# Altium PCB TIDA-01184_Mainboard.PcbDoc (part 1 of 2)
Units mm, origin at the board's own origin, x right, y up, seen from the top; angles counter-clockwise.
Board outline 127 x 101.6 mm, 4 copper layers (L1 - TOP Component, L2 - GND, L3 - VCC, L4 - BOTTOM Solder), stack 0.844 mm thick; 127 components, 87 nets, 414 pads, 196 vias.
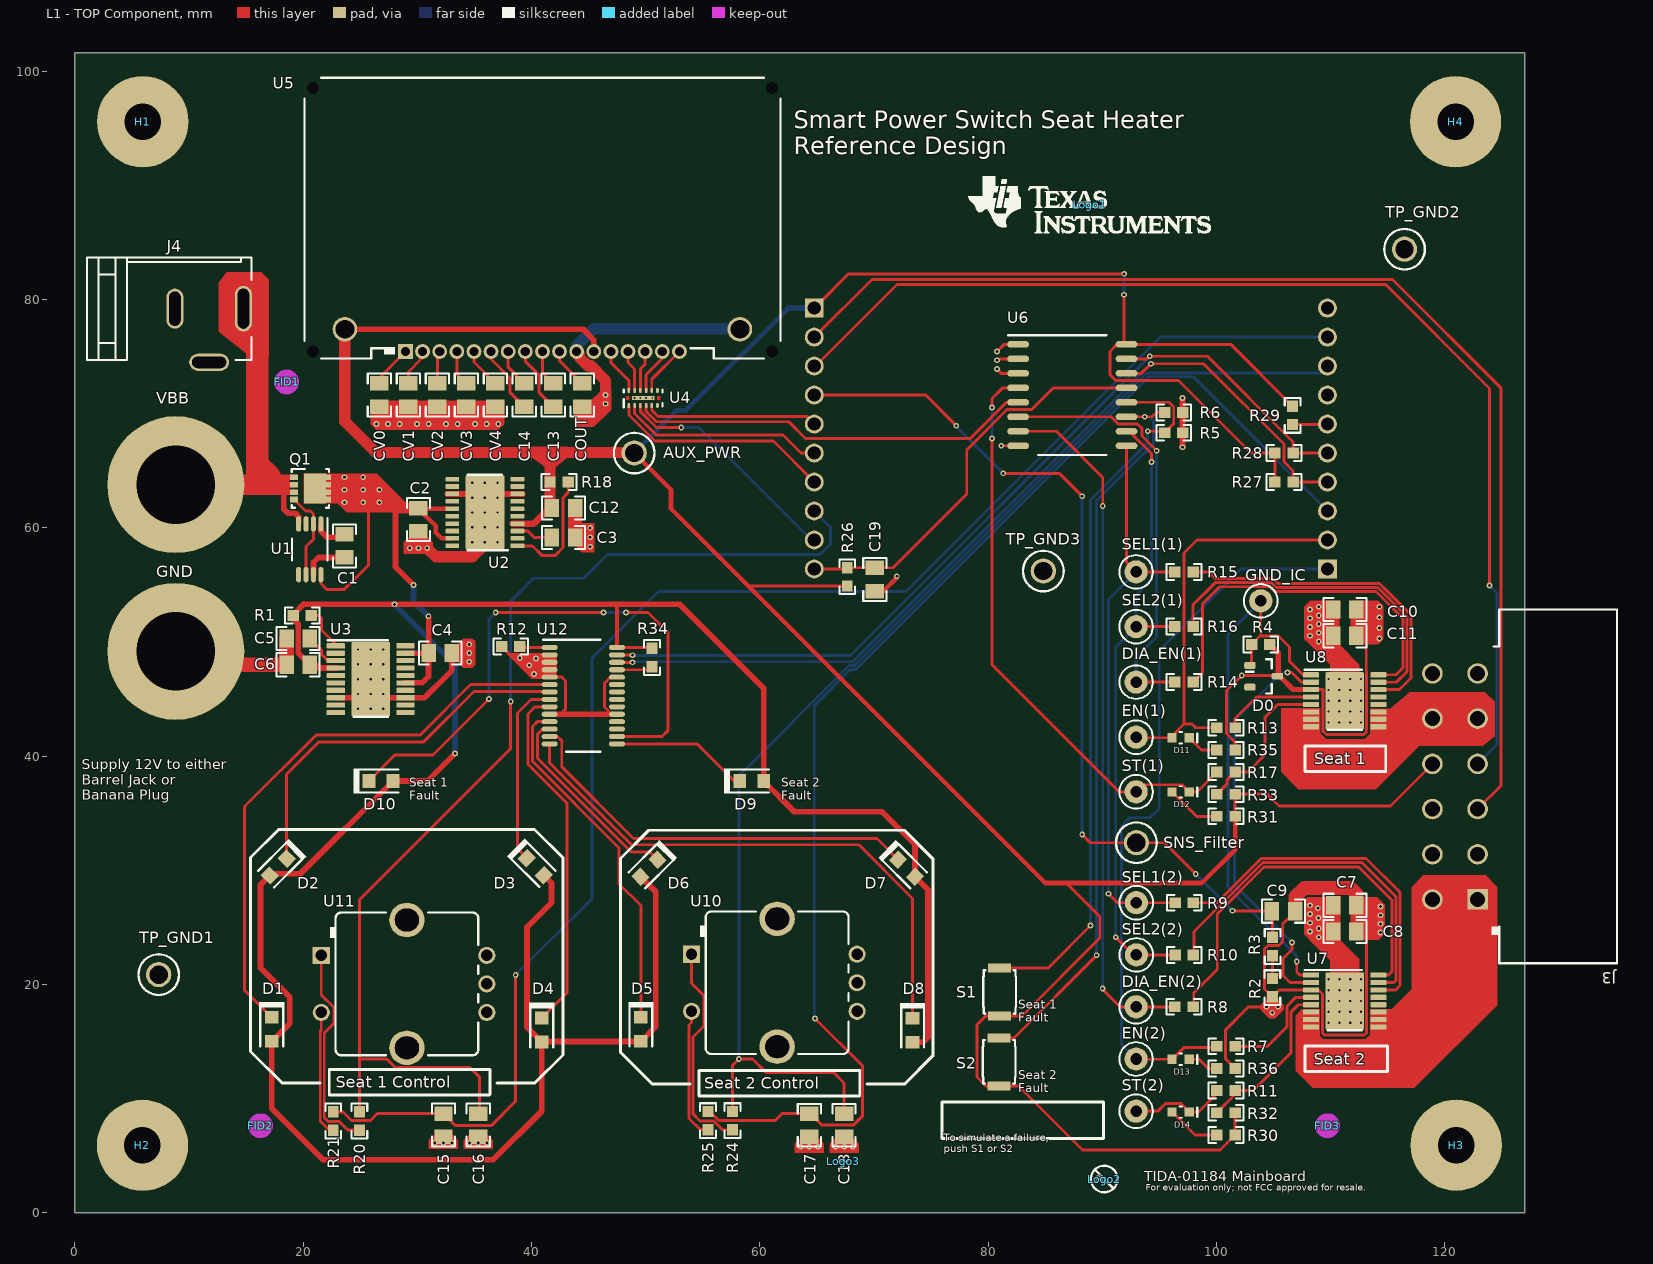
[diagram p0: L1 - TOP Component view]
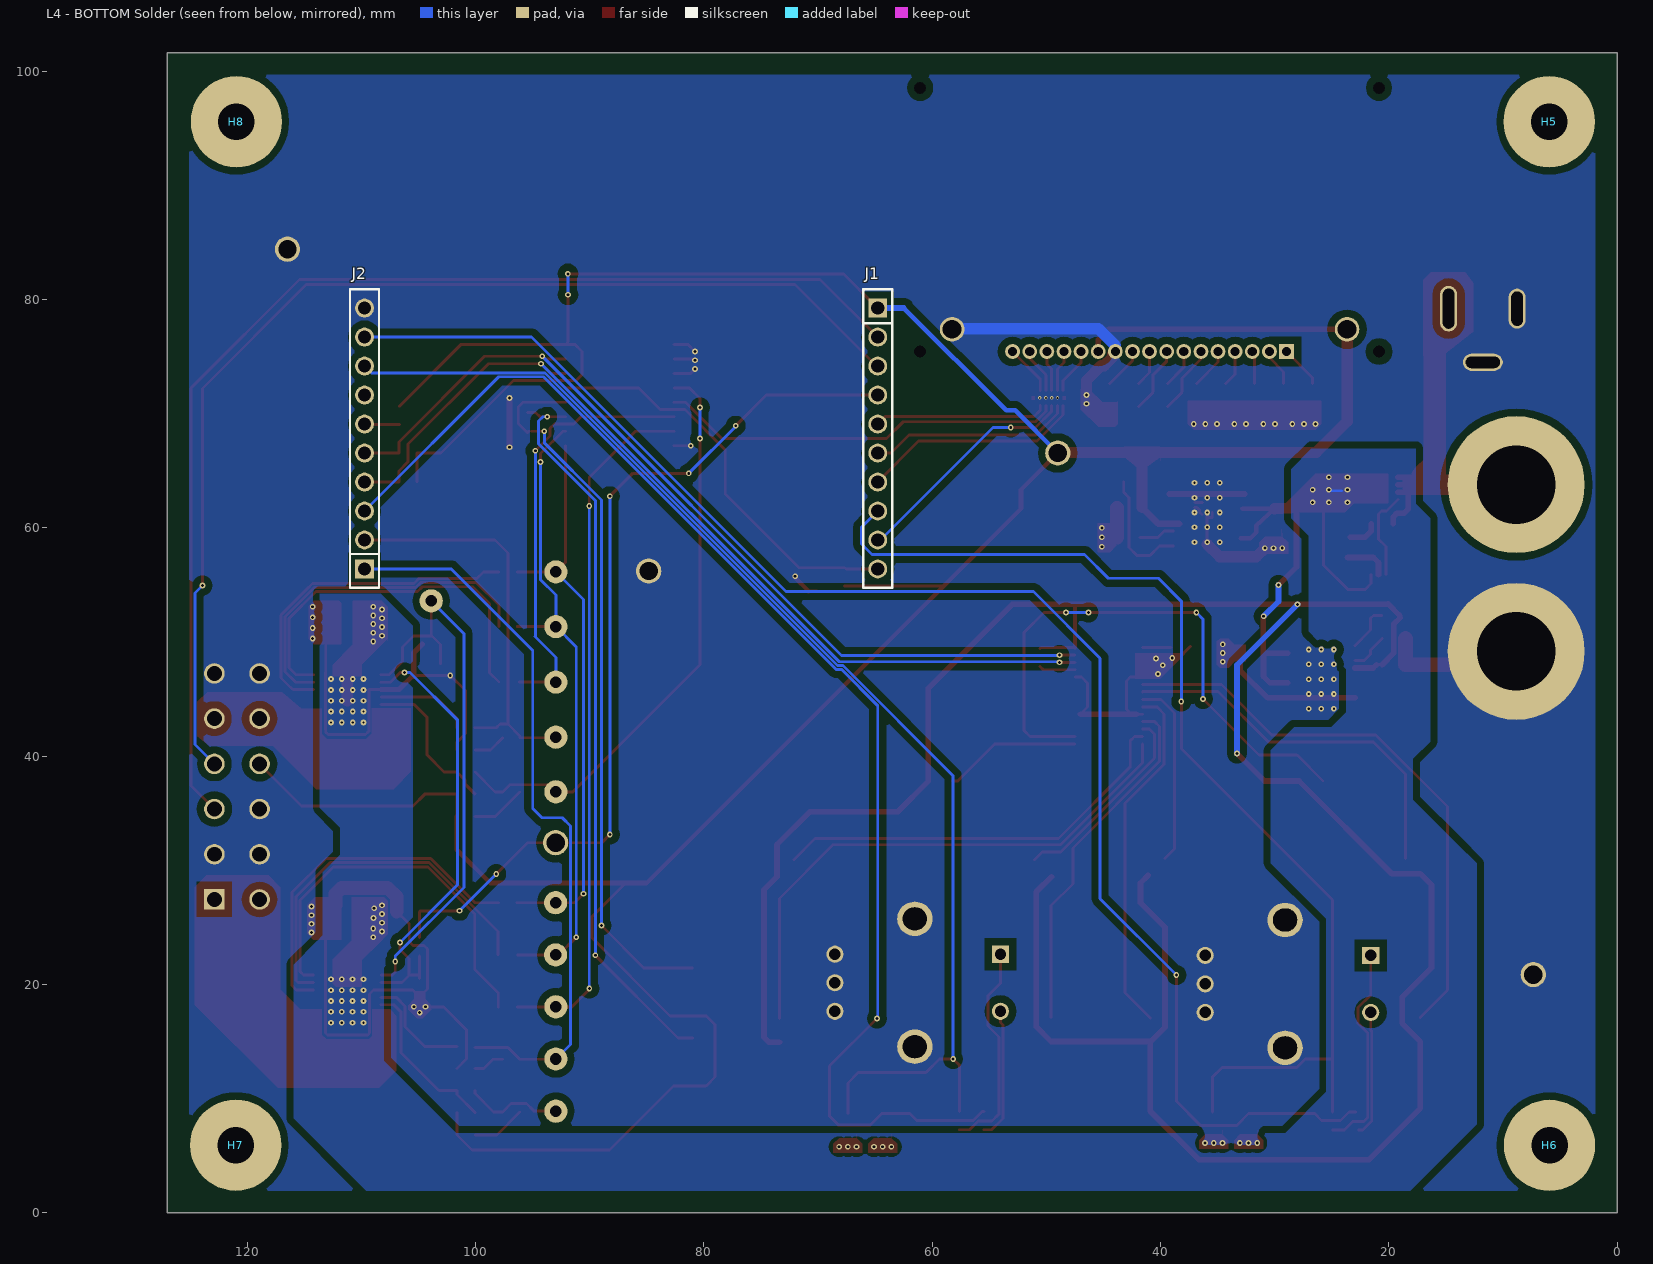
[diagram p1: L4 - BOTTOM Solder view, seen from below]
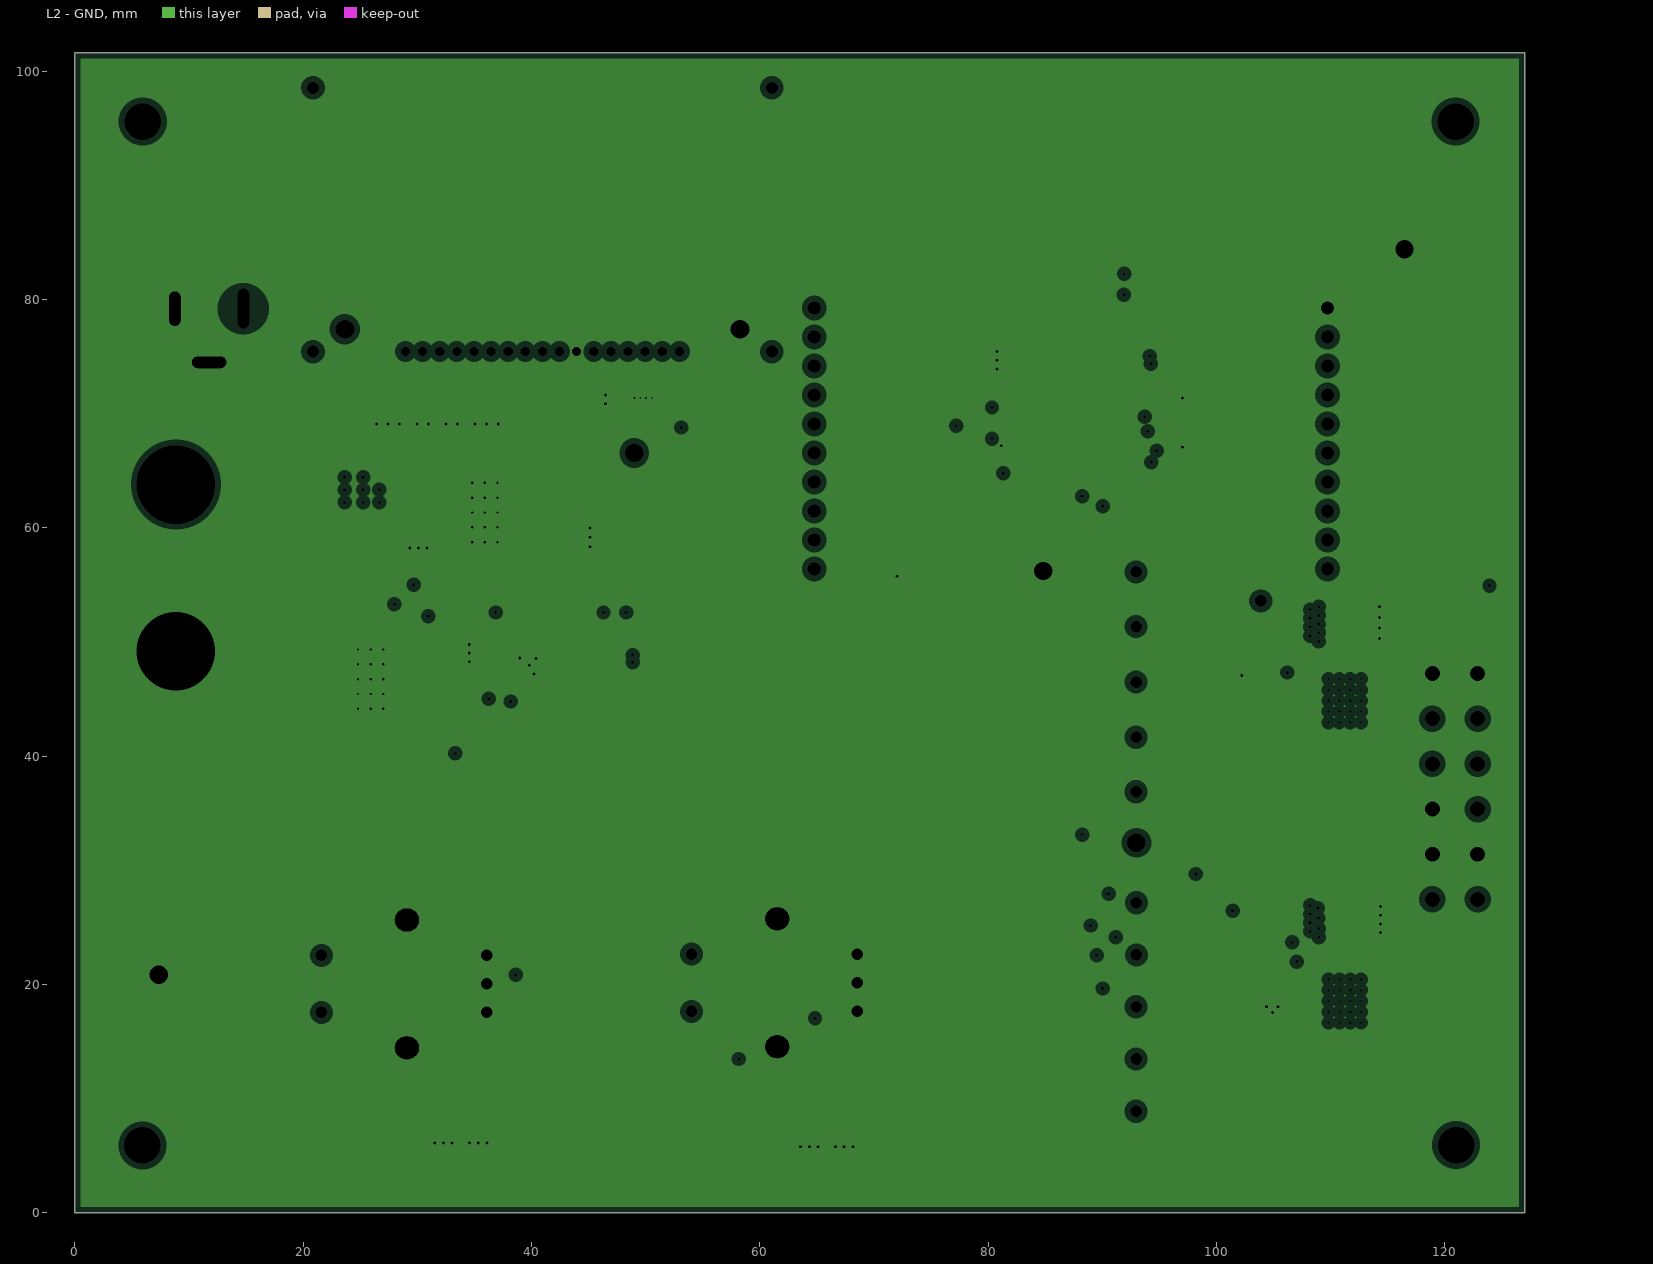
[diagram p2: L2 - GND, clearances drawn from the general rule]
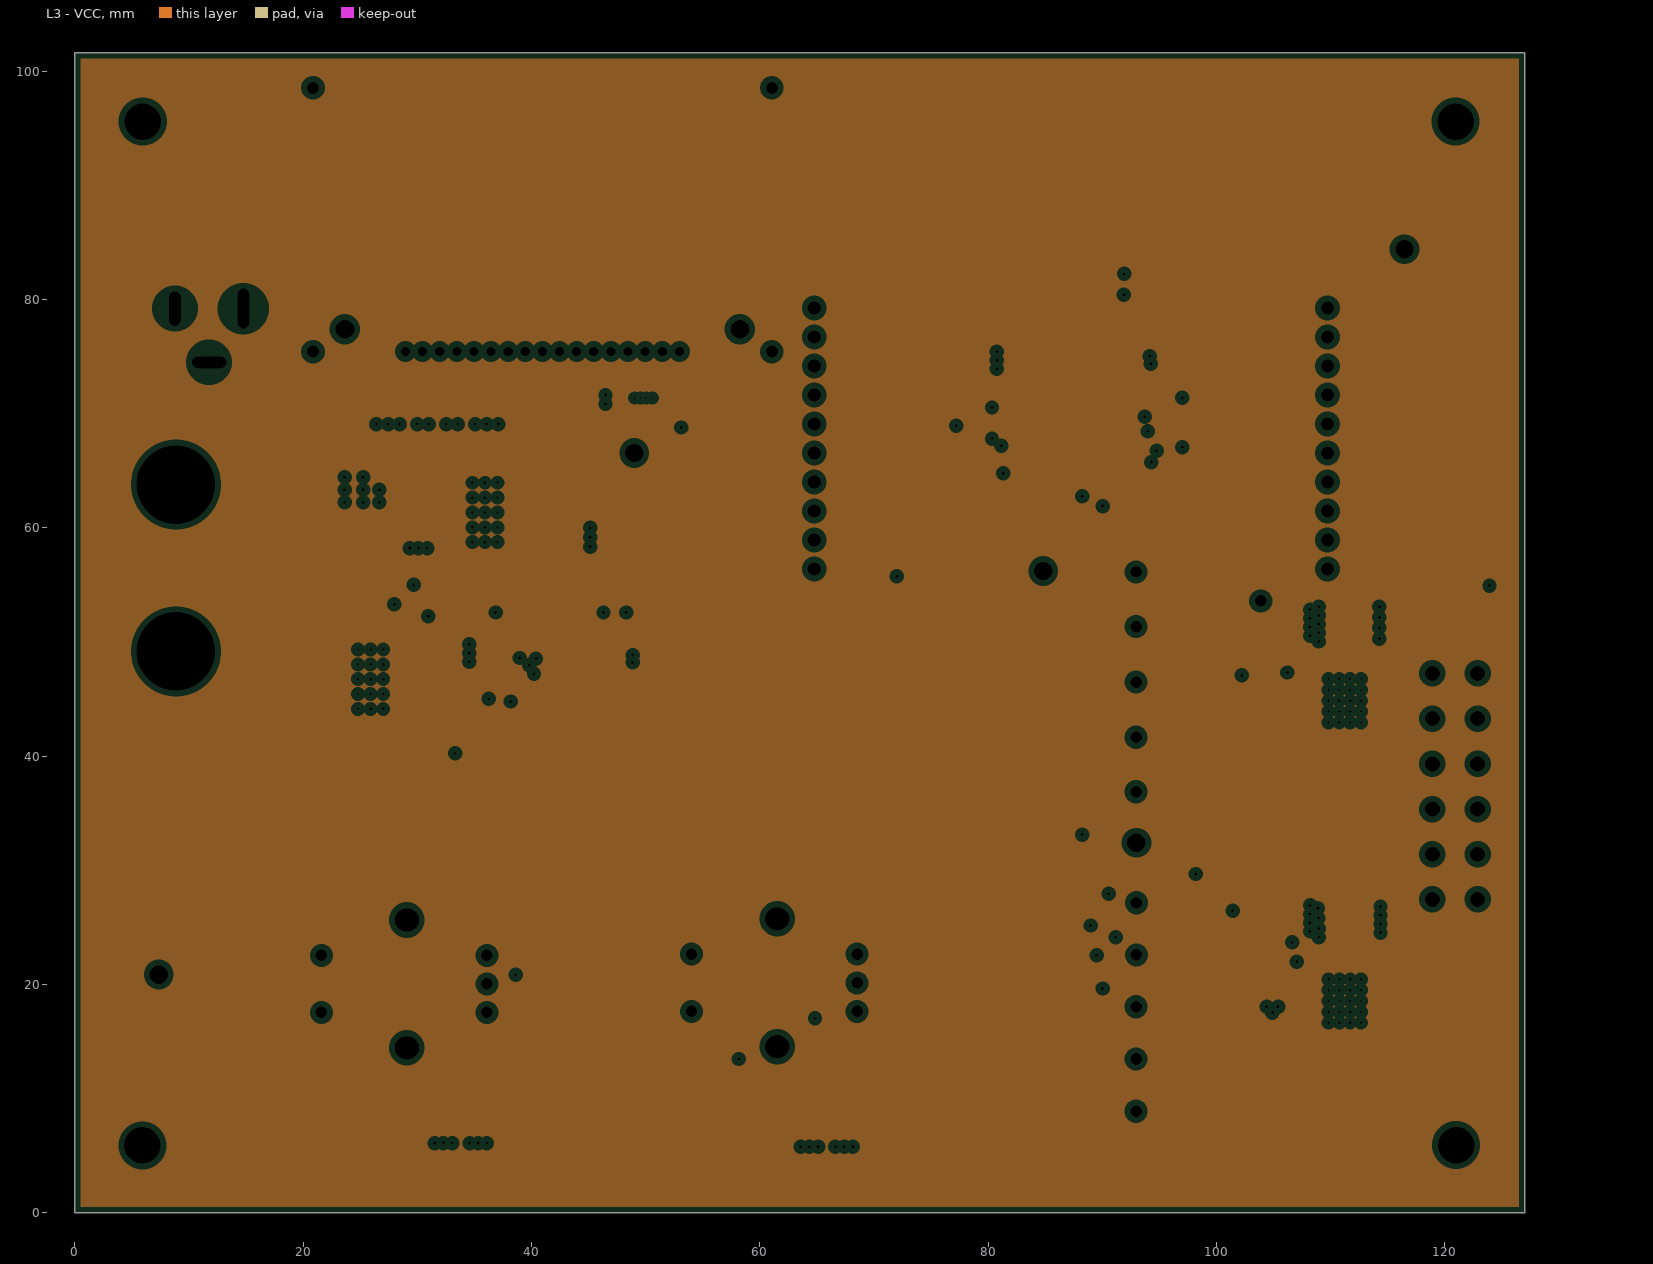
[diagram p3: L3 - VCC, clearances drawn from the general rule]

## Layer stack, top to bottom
Top Solder: solder mask 0.0102, Solder Resist, Dk 3.5
L1 - TOP Component: signal copper 0.0356
Dielectric 1: core 0.32, FR-4, Dk 4.8
L2 - GND: plane copper 0.036, net GND
Dielectric 3: prepreg 0.127, Dk 4.2
L3 - VCC: plane copper 0.036
Dielectric 4: core 0.254, Dk 4.2
L4 - BOTTOM Solder: signal copper 0.0356
Bottom Solder: solder mask 0.0102, Solder Resist, Dk 3.5

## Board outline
0,0 0,101.6 127,101.6 127,0

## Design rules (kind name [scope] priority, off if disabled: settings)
AcuteAngle [All] p1: minimum=4.50000000000000E+0001 checktracksonly=FALSE
AssemblyTestPointUsage [All] p1: valid=2
BoardOutlineClearance BoardOutlineClearance_MountingHoles [OnCopper and InComponentClass('Mounting Holes')] p1: gap=1.016 ignorepadtopadclearanceinfootprint=FALSE
BoardOutlineClearance BoardOutlineClearance_Poly [OnCopper and InPoly] p2: gap=0.635 ignorepadtopadclearanceinfootprint=FALSE
BoardOutlineClearance [OnCopper and Not InComponentClass('Logo') and not InComponentClass('FiducialMark') and not InRegion(1000,500,4000,800)] p3: gap=1.905 ignorepadtopadclearanceinfootprint=FALSE
Clearance Clearance_Keepouts [((IsTrack Or IsArc) And Not InPoly) And IsFree and IsKeepOut vs ((IsTrack Or IsArc) And Not InPoly) And IsFree and IsKeepOut] p1: gap=0 ignorepadtopadclearanceinfootprint=FALSE
Clearance Clearance_Poly [InPolygon] p2: gap=0.635 ignorepadtopadclearanceinfootprint=FALSE except(0: Arc-Hole Track-Hole SMDPad-Hole THPad-Hole Via-Hole Fill-Hole Poly-Hole Region-Hole Text-Hole)
Clearance [All] p3: gap=0.076 ignorepadtopadclearanceinfootprint=FALSE except(0: Arc-Hole Track-Hole SMDPad-Hole THPad-Hole Via-Hole Fill-Hole Poly-Hole Region-Hole Text-Hole)
ComponentClearance ComponentClearance_MountingHoles_FiducialMarks [InComponentClass('Mounting Holes') vs InComponentClass('FiducialMark')] p1: gap=1.27 collisioncheckmode=3 verticalgap=0.254 showdistances=FALSE
ComponentClearance ComponentClearance_Shunt [InComponentClass('Header') vs InComponentClass('Shunt')] p2: gap=0 collisioncheckmode=3 verticalgap=0 showdistances=FALSE
ComponentClearance ComponentClearance_Logo [InComponentClass('Logo')] p3: gap=1.27 collisioncheckmode=3 verticalgap=0.254 showdistances=FALSE
ComponentClearance ComponentClearance_ScrewToNut [(HasFootprint('NY PMS 440 0025 PH')) vs (HasFootprint('Keystone_1902C'))] p4: gap=0.076 collisioncheckmode=3 verticalgap=0.254 showdistances=FALSE
ComponentClearance ComponentClearance_MountingHoles [InComponentClass('Mounting Holes')] p5: gap=1 collisioncheckmode=3 verticalgap=2540 showdistances=FALSE
ComponentClearance ComponentClearance_SmallPassives [HasFootprint('0201*') or HasFootprint('0402*') or HasFootprint('0508') or HasFootprint('0603*') or HasFootprint('0612') or HasFootprint('0805*') or HasFootprint('0815*') or HasFootprint('0830*') or HasFootprint('1206*') or HasFootprint('1210*') or HasFootprint('1808*') or HasFootprint('1812*') or HasFootprint('1825*') or HasFootprint('2010*') or HasFootprint('2220*') or HasFootprint('2225*') or HasFootprint('2512*') or HasFootprint('2728*') or HasFootprint('3518*') vs HasFootprint('0201*') or HasFootprint('0402*') or HasFootprint('0508') or HasFootprint('0603*') or HasFootprint('0612') or HasFootprint('0805*') or HasFootprint('0815*') or HasFootprint('0830*') or HasFootprint('1206*') or HasFootprint('1210*') or HasFootprint('1808*') or HasFootprint('1812*') or HasFootprint('1825*') or HasFootprint('2010*') or HasFootprint('2220*') or HasFootprint('2225*') or HasFootprint('2512*') or HasFootprint('2728*') or HasFootprint('3518*')] p6: gap=0.38 collisioncheckmode=3 verticalgap=0.254 showdistances=FALSE
ComponentClearance ComponentClearance_THtoSMT [IsThruComponent vs IsSMTComponent] p7: gap=1.016 collisioncheckmode=3 verticalgap=0.762 showdistances=FALSE
ComponentClearance ComponentClearance_THtoTH [IsThruComponent vs IsThruComponent] p8: gap=0.762 collisioncheckmode=3 verticalgap=0.762 showdistances=FALSE
ComponentClearance [All] p9: gap=0.762 collisioncheckmode=3 verticalgap=0.254 showdistances=FALSE
DiffPairsRouting [All] p1: maxlimit=2.54 minlimit=0.254 mostfreqgap=0.254 toplayer_minwidth=0.381 toplayer_maxwidth=0.381 toplayer_prefwidth=0.381 bottomlayer_minwidth=0.381 bottomlayer_maxwidth=0.381 bottomlayer_prefwidth=0.381 maxuncoupledlength=25.4
FabricationTestPointUsage TestPointUsage [All] p1: valid=2 allowmultiple=FALSE
FabricationTestpoint Testpoint [All] p1: side=3 testpointundercomponent=TRUE minsize=1.016 maxsize=2.54 preferedsize=1.524 minholesize=0 maxholesize=1.016 preferedholesize=0.813 testpointgrid=0.025 allowsidetop=TRUE allowsidebottom=TRUE usegrid=TRUE gridtolerance=0
FanoutControl Fanout_LCC [IsLCC] p1: bgadir=Out bgaviamode=Centered fanoutstyle=Auto fanoutdirection=Alternating viagrid=0.025 // Fanout_LCC (Default Rule)
FanoutControl Fanout_BGA [IsBGA] p2: bgadir=Out bgaviamode=Centered fanoutstyle=Auto fanoutdirection=Alternating viagrid=0.025 // Fanout_BGA (Default Rule)
FanoutControl Fanout_Default [All] p4: bgadir=Out bgaviamode=Centered fanoutstyle=Auto fanoutdirection=Alternating viagrid=0.025 // Fanout_Default (Default Rule)
FanoutControl Fanout_Small [(CompPinCount < 5)] p5: bgadir=Out bgaviamode=Centered fanoutstyle=Auto fanoutdirection=OutThenIn viagrid=0.025 // Fanout_Small (Default Rule)
HoleSize [All] p1: absolutevalues=TRUE maxlimit=7.62 minlimit=0.127 maxpercent=80.000 minpercent=20.000
MinimumAnnularRing MinimumAnnularRing_ThermalPadVias [IsVia and InAnyComponent] p1: minimumring=0.15
MinimumAnnularRing [All] p2: minimumring=0.051
MinimumSolderMaskSliver MinimumSolderMaskSliver_Logo [InComponentClass('Logo') vs InComponentClass('Logo')] p1: minsoldermaskwidth=0.018
MinimumSolderMaskSliver [All] p2: minsoldermaskwidth=0.1
PlaneClearance [All] p1: clearance=0.508
PlaneConnect [All] p1: planeconnectstyle=Relief reliefexpansion=0.254 reliefentries=4 reliefconductorwidth=0.254 reliefairgap=0.254
PolygonConnect [All] p1: connectstyle=Direct reliefconductorwidth=0.254 reliefentries=4 polygonreliefangle="90 Angle" airgapwidth=0.254
RoutingVias ThermalPadVias [IsVia and InAnyComponent] p1: holewidth=0.2 width=0.5 viastyle="Through Hole" minholewidth=0.2 minwidth=0.254 maxholewidth=0.33 maxwidth=0.762
RoutingVias [All] p2: holewidth=0.406 width=0.864 viastyle="Through Hole" minholewidth=0.127 minwidth=0.254 maxholewidth=1.016 maxwidth=1.651
SilkToBoardRegionClearance [Not ((IsComment or IsDesignator) And (Hide <> 'False')) and not InRegion(1000,500,4000,800)] p1:
SilkToSilkClearance SilkToSilkClearance_Pb-FreeLogo [(HasFootprint('Pb-Free_Overlay_Medium') OR HasFootprint('Pb-Free_Overlay_Small')) vs (HasFootprint('Pb-Free_Overlay_Medium') OR HasFootprint('Pb-Free_Overlay_Small'))] p1: silktosilkclearance=0
SilkToSilkClearance [All] p2: silktosilkclearance=0.064
SilkToSolderMaskClearance SilkToComponentPadClearance [IsPad and InAnycomponent] p1: minsilkscreentomaskgap=0.076 clearancetoexposedcopper=TRUE
SilkToSolderMaskClearance "Silk to Solder Mask Opening" [All] p2: minsilkscreentomaskgap=0.019 clearancetoexposedcopper=FALSE
SolderMaskExpansion [All] p1: expansion=0.05
Width [All] p1: maxlimit=2.54 minlimit=0.152 preferedwidth=0.254 checkconnectedcopper=TRUE
14 further rules are at their usual default settings.

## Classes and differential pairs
component class TIDA-01184_EVM_Hardware: !PCB FID1 FID2 FID3 H1 H2 H3 H4 H5 H6 H7 H8 Logo1 Logo2 Logo3 ZZ1 ZZ2 ZZ3 ZZ4
component class "Mounting Holes": H1 H2 H3 H4
component class Logo: Logo1
component class FiducialMark: FID1 FID2 FID3
component class AssemblyNote: ZZ1 ZZ2 ZZ3 ZZ4
component class TIDA-01184_Digital: C13 C14 C19 COUT CV0 CV1 CV2 CV3 CV4 D11 D12 D13 D14 J1 J2 R5 R6 R26 R27 R28 R29 R30 R31 R35 R36 S1 S2 U4 U5 U6
component class TIDA-01184_Power: AUX_PWR C1 C2 C3 C4 C5 C6 C12 GND J4 Q1 R1 R18 U1 U2 U3 VBB
component class TIDA-01184_LED_Drivers: C15 C16 C17 C18 D1 D2 D3 D4 D5 D6 D7 D8 D9 D10 R12 R20 R21 R24 R25 R34 U10 U11 U12
component class TIDA-01184_Load_Card: J3
component class TIDA-01184_HighSideDrivers: C7 C8 C9 C10 C11 D0 DIA_EN(1) DIA_EN(2) EN(1) EN(2) GND_IC R2 R3 R4 R7 R8 R9 R10 R11 R13 R14 R15 R16 R17 R32 R33 SEL1(1) SEL1(2) SEL2(1) SEL2(2) SNS_Filter ST(1) ST(2) TP_GND1 TP_GND2 TP_GND3 U7 U8

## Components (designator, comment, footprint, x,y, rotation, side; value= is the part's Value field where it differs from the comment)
AUX_PWR "5010" Keystone5010 48.997,66.548 r90 top
C1 "C0805C104M5RACTU" 0805_HV 23.622,58.42 r90 top
C2 "C0805C104M5RACTU" 0805_HV 30.087,60.716 r270 top
C3 "C0805C104M5RACTU" 0805_HV 42.799,59.153 r0 top
C4 "C0805C104M5RACTU" 0805_HV 32.004,49.022 r0 top
C5 "C0805C104M5RACTU" 0805_HV 19.558,50.292 r180 top
C6 "C0805C104M5RACTU" 0805_HV 19.558,48.006 r180 top
C7 "C0805C104M5RACTU" 0805_HV 111.252,26.924 r180 top
C8 "C0805C104M5RACTU" 0805_HV 111.252,24.638 r180 top
C9 "C0805C104M5RACTU" 0805_HV 105.884,26.415 r0 top
C10 "C0805C104M5RACTU" 0805_HV 111.252,52.832 r180 top
C11 "C0805C104M5RACTU" 0805_HV 111.252,50.546 r180 top
C12 "C0805C104M5RACTU" 0805_HV 42.799,61.743 r0 top
C13 "C0805C104M5RACTU" 0805_HV 41.91,71.628 r90 top
C14 "C0805C104M5RACTU" 0805_HV 39.37,71.628 r270 top
C15 "C0805C104M5RACTU" 0805_HV 32.283,7.671 r270 top
C16 "C0805C104M5RACTU" 0805_HV 35.331,7.671 r270 top
C17 "C0805C104M5RACTU" 0805_HV 64.339,7.656 r270 top
C18 "C0805C104M5RACTU" 0805_HV 67.387,7.656 r270 top
C19 "C0805C104M5RACTU" 0805_HV 70.079,55.474 r90 top
COUT "C0805C104M5RACTU" 0805_HV 44.45,71.628 r90 top
CV0 "C0805C104M5RACTU" 0805_HV 26.67,71.628 r90 top
CV1 "C0805C104M5RACTU" 0805_HV 29.21,71.628 r90 top
CV2 "C0805C104M5RACTU" 0805_HV 31.75,71.628 r90 top
CV3 "C0805C104M5RACTU" 0805_HV 34.29,71.628 r90 top
CV4 "C0805C104M5RACTU" 0805_HV 36.83,71.628 r90 top
D0 "BAS21-7-F" SOT-23 104.14,46.99 r0 top
D1 "150080BS75000" WL-SMCW_Blue_0805 17.247,16.053 r270 top
D2 "150080BS75000" WL-SMCW_Blue_0805 17.805,30.277 r225 top
D3 "150080BS75000" WL-SMCW_Blue_0805 40.335,30.302 r315 top
D4 "150080BS75000" WL-SMCW_Blue_0805 40.895,16.002 r270 top
D5 "150080BS75000" WL-SMCW_Blue_0805 49.581,16.053 r270 top
D6 "150080BS75000" WL-SMCW_Blue_0805 50.292,30.176 r225 top
D7 "150080BS75000" WL-SMCW_Blue_0805 72.847,30.175 r315 top
D8 "150080BS75000" WL-SMCW_Blue_0805 73.381,15.977 r270 top
D9 "150080SS75000" WL-SMCW_RED_0805 59.284,37.817 r0 top
D10 "150080SS75000" WL-SMCW_RED_0805 26.813,37.817 r0 top
D11 "LG L29K-G2J1-24-Z" "LG L29K_GREEN" 96.876,41.605 r0 top
D12 "LG L29K-G2J1-24-Z" "LG L29K_GREEN" 96.876,36.855 r0 top
D13 "LG L29K-G2J1-24-Z" "LG L29K_GREEN" 96.876,13.437 r0 top
D14 "LG L29K-G2J1-24-Z" "LG L29K_GREEN" 96.876,8.814 r0 top
DIA_EN(1) "5002" Keystone5002 92.964,46.482 r90 top
DIA_EN(2) "5002" Keystone5002 92.964,18.034 r90 top
EN(1) "5002" Keystone5002 92.964,41.656 r90 top
EN(2) "5002" Keystone5002 92.964,13.462 r90 top
FID1 "Fiducial" Fiducial10-20 18.542,72.774 r0 top
FID2 "Fiducial" Fiducial10-20 16.256,7.62 r0 top
FID3 "Fiducial" Fiducial10-20 109.728,7.62 r0 top
GND "108-0740-001" Johnson_108-0740-001 8.839,49.174 r90 top
GND_IC "5002" Keystone5002 103.886,53.594 r90 top
H1 "NY PMS 440 0025 PH" "NY PMS 440 0025 PH" 5.944,95.58 r0 top
H2 "NY PMS 440 0025 PH" "NY PMS 440 0025 PH" 5.918,5.893 r90 top
H3 "NY PMS 440 0025 PH" "NY PMS 440 0025 PH" 121.006,5.918 r90 top
H4 "NY PMS 440 0025 PH" "NY PMS 440 0025 PH" 120.955,95.58 r90 top
H5 "1902C" Keystone_1902C 5.944,95.58 r0 bottom
H6 "1902C" Keystone_1902C 5.918,5.893 r180 bottom
H7 "1902C" Keystone_1902C 121.006,5.918 r180 bottom
H8 "1902C" Keystone_1902C 120.955,95.58 r180 bottom
J1 "SSW-110-23-F-S" CONN_SSW-110-23-F-S 64.77,67.818 r90 bottom
J2 "SSW-110-23-F-S" CONN_SSW-110-23-F-S 109.728,67.818 r270 bottom
J3 "EBM06DRAN" Sullins_xxM06DRAN 120.904,37.338 r180 top
J4 "PJ-202BH" CUI_PJ-202BH 14.757,79.197 r180 top
Logo1 "Texas Instruments" TI_Stacked_Overlay_Small 88.9,88.29 r0 top
Logo2 "Pb-Free Symbol" Pb-Free_Overlay_Small 90.17,2.946 r0 top
Logo3 "FCC disclaimer" FCC_disclaimer 67.31,4.521 r0 top
Q1 "CSD17577Q3A" TRANS_NexFET_Q3A 20.826,63.45 r0 top
R1 "RC0603JR-071KL" 0603 19.914,52.324 r0 top
R2 "RC0603FR-072K2L" 0603 104.902,19.712 r90 top
R3 "CRCW060310K0JNEA" 0603 104.927,23.317 r270 top
R4 "RC0603JR-071KL" 0603 103.886,49.784 r180 top
R5 "RC0603JR-071KL" 0603 96.266,68.326 r0 top
R6 "RC0603JR-071KL" 0603 96.266,70.104 r0 top
R7 "CRCW060310K0JNEA" 0603 100.838,14.573 r0 top
R8 "CRCW060310K0JNEA" 0603 97.155,18.034 r0 top
R9 "CRCW060310K0JNEA" 0603 97.18,27.153 r0 top
R10 "CRCW060310K0JNEA" 0603 97.18,22.581 r0 top
R11 "CRCW060310K0JNEA" 0603 100.838,10.69 r0 top
R12 "RC0603JR-071KL" 0603 38.186,49.607 r0 top
R13 "CRCW060310K0JNEA" 0603 100.838,42.478 r0 top
R14 "CRCW060310K0JNEA" 0603 97.155,46.482 r0 top
R15 "CRCW060310K0JNEA" 0603 97.155,56.134 r0 top
R16 "CRCW060310K0JNEA" 0603 97.155,51.341 r0 top
R17 "CRCW060310K0JNEA" 0603 100.838,38.6 r0 top
R18 "RC0603JR-071KL" 0603 42.418,64.008 r0 top
R20 "CRCW060310K0JNEA" 0603 24.917,8.027 r90 top
R21 "CRCW060310K0JNEA" 0603 22.631,8.027 r90 top
R24 "CRCW060310K0JNEA" 0603 57.615,8.063 r90 top
R25 "CRCW060310K0JNEA" 0603 55.456,8.063 r90 top
R26 "CRCW060310K0JNEA" 0603 67.666,55.702 r270 top
R27 "CRCW060310K0JNEA" 0603 105.918,64.008 r180 top
R28 "CRCW060310K0JNEA" 0603 105.918,66.548 r180 top
R29 "RC0603FR-0747KL" 0603 106.68,69.85 r90 top
R30 "RC0603FR-071K65L" 0603 100.838,6.807 r0 top
R31 "RC0603FR-071K65L" 0603 100.838,34.722 r0 top
R32 "RC1608J103CS" 0603 100.838,8.75 r0 top
R33 "RC1608J103CS" 0603 100.838,36.661 r0 top
R34 "CRCW060310K0FKEA" 0603 50.546,48.641 r270 top
R35 "RC0603FR-071K65L" 0603 100.838,40.541 r180 top
R36 "RC0603FR-071K65L" 0603 100.838,12.633 r180 top
S1 "SKRKAEE010" SW_SKRKAEE010 81.002,19.333 r90 top
S2 "SKRKAEE010" SW_SKRKAEE010 80.968,13.205 r90 top
SEL1(1) "5002" Keystone5002 92.964,56.134 r90 top
SEL1(2) "5002" Keystone5002 92.989,27.153 r90 top
SEL2(1) "5002" Keystone5002 92.964,51.341 r90 top
SEL2(2) "5002" Keystone5002 92.989,22.581 r90 top
SNS_Filter "5010" Keystone5010 92.989,32.41 r90 top
ST(1) "5002" Keystone5002 92.964,36.868 r90 top
ST(2) "5002" Keystone5002 92.964,8.89 r90 top
TP_GND1 "5011" Keystone5011 7.341,20.853 r90 top
TP_GND2 "5011" Keystone5011 116.484,84.404 r90 top
TP_GND3 "5011" Keystone5011 84.836,56.21 r90 top
U1 "LM74610QDGKRQ1" DGK0008A_N 20.572,58.116 r270 top
U2 "TPS7B6733QPWPRQ1" PWP0020D_L 35.915,61.341 r180 top
U3 "TPS7B6750QPWPRQ1" PWP0020D_M 25.908,46.736 r0 top
U4 "TPD6F002QDSVRQ1" DSV0012A 49.784,71.374 r90 top
U5 "NHD-C12832A1Z-FSW-FBW-3V3" NHD-C12832A1Z-FSW-FBW-3V3 28.956,75.438 r90 top
U6 "PCF8574ADW" DW0016A_N 87.376,71.628 r0 top
U7 "TPS1HA08AQPWPRQ1" TPS1HA08-Q1_N 111.252,18.542 r0 top
U8 "TPS1HA08AQPWPRQ1" TPS1HA08-Q1_N 111.24,44.846 r0 top
U10 "EVE-JBBF2020B" Panasonic_EVE-JBBF2020B 61.519,20.141 r0 top
U11 "EVE-JBBF2020B" Panasonic_EVE-JBBF2020B 29.083,20.041 r0 top
U12 "TLC59116ITPWRQ1" PW0028A_N 44.536,45.289 r0 top
VBB "108-0740-001" Johnson_108-0740-001 8.839,63.779 r0 top
ZZ1 "This Assembly Note is for PCB labels only" AssemblyNoteLabel 1.778,113.284 r0 top
ZZ2 "These assemblies are ESD sensitive, ESD precautions shall be observed." AssemblyNote 1.651,110.975 r0 top
ZZ3 "These assemblies must be clean and free from flux and all contaminants. Use of no clean flux is not acceptable." AssemblyNote 1.651,108.726 r0 top
ZZ4 "These assemblies must comply with workmanship standards IPC-A-610 Class 2, unless otherwise specified." AssemblyNote 1.651,106.477 r0 top

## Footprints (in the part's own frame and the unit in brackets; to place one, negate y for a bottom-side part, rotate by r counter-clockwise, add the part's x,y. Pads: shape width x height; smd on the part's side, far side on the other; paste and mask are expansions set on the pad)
0603 [mm] "0603 from SM-752 data"
  rect 1x0.95 smd: 1(-0.8,0) 2(0.8,0)
  silkscreen extent -1.52,-0.69 1.52,0.69, body extent -0.87,-0.47 0.87,0.47, height 1
0805_HV [mil] "0805 with 30mil clearance between pads"
  rect 50x63 smd: 1(-40,0) 2(40,0)
  silkscreen extent -74,-40 74,40, body extent -43,-29 43,29, height 57
AssemblyNote [mm] "Assembly Note"
AssemblyNoteLabel [mm] "Assembly Note for PCB Labels"
CONN_SSW-110-23-F-S [mm] "SAMTEC"
  rect 1.65x1.65 hole 1.15: 1(11.43,0)
  round 1.65 hole 1.15: 2(8.89,0) 3(6.35,0) 4(3.81,0) 5(1.27,0) 6(-1.27,0) 7(-3.81,0) 8(-6.35,0) 9(-8.89,0) 10(-11.43,0)
  silkscreen extent -13.08,-1.27 13.08,1.27, body extent -13,-1.27 13,1.27, height 8.59
CUI_PJ-202BH [mm] "DC Jack, Center Pin 2.5 mm"
  oval 1.5x4 hole 1 slot 3.5 at 90 deg: 1(0,0)
  oval 1.5x3.5 hole 1 slot 3 at 90 deg: 2(6,0)
  oval 3.5x1.5 hole 1 slot 3 at 0 deg: 3(3,4.7)
  silkscreen extent -0.7,-4.5 13.7,4.5, body extent -0.75,-4.5 13.65,4.9, height 11.02
DGK0008A_N [mm] "TSOP, 8-Leads, Body 3x3mm, Pitch 0.65mm, IPC Medium Density"
  oval 1.35x0.45 smd: 1(-2.225,0.975) 2(-2.225,0.325) 3(-2.225,-0.325) 4(-2.225,-0.975) 5(2.225,-0.975) 6(2.225,-0.325) 7(2.225,0.325) 8(2.225,0.975)
  silkscreen extent -2.75,-1.55 0.95,1.55, body extent -2.45,-1.5 2.45,1.5, height 0.96
DSV0012A [mm] "SON, 12-Leads, Body 1.35x3mm, Pitch 0.5mm, Thermal Pad 2x0.35mm, TI Recommended"
  oval 0.45x0.225 smd: 1(-0.65,1.25) 2(-0.65,0.75) 3(-0.65,0.25) 4(-0.65,-0.25) 5(-0.65,-0.75) 6(-0.65,-1.25) 7(0.65,-1.25) 8(0.65,-0.75) 9(0.65,-0.25) 10(0.65,0.25) 11(0.65,0.75) 12(0.65,1.25)
  rect 0.35x2 smd paste-0.175: 13(0,0)
  L1 - TOP Component region: -0.174,-1.501 0.176,-1.501 0.176,-1.201 -0.174,-1.201
  L1 - TOP Component region: -0.174,1.199 0.176,1.199 0.176,1.499 -0.174,1.499
  silkscreen extent -0.82,-1.7 0.72,1.7, body extent -0.72,-1.55 0.72,1.55, height 0.81
DW0016A_N [mm] "SOIC, 16-Leads, Body 10.3x7.5mm, Pitch 1.27mm, IPC Medium Density"
  oval 1.9x0.6 smd: 1(-4.75,4.445) 2(-4.75,3.175) 3(-4.75,1.905) 4(-4.75,0.635) 5(-4.75,-0.635) 6(-4.75,-1.905) 7(-4.75,-3.175) 8(-4.75,-4.445) 9(4.75,-4.445) 10(4.75,-3.175) 11(4.75,-1.905) 12(4.75,-0.635) 13(4.75,0.635) 14(4.75,1.905) 15(4.75,3.175) 16(4.75,4.445)
  silkscreen extent -5.6,-5.25 3,5.25, body extent -5.14,-5.13 5.14,5.13, height 2.54
FCC_disclaimer [mm]
Fiducial10-20 [mm]
  round 1 smd mask+0.5: 1(0,0)
  L1 - TOP Component keep-out circle w1.178: c0,0 r0.5
Johnson_108-0740-001 [mm] "Banana Jack Uninsulated Standard Type"
  round 12 hole 6.858: 1(0,0)
  body extent -4.77,-5.43 4.75,5.57, height 2.39
Keystone5002 [mil] "For Keystone 500x miniature loop terminals"
  round 80 hole 40: 1(0,0)
  silkscreen extent -58,-58 58,58, body extent -49,-49 49,49, height 182
Keystone5010 [mil] "Keystone Multipurpose loops"
  round 87 hole 63: 1(0,0)
  silkscreen extent -70,-70 70,70, body extent -63,-63 63,62, height 319
Keystone5011 [mil] "Keystone Multipurpose loops"
  round 87 hole 63: 1(0,0)
  silkscreen extent -70,-70 70,70, body extent -63,-63 63,62, height 319
Keystone_1902C [mil] "Hex Standoff, 4-40 threaded, nylon"
  round 1 on Mech4: 0(0,0)
  body extent -145,-126 146,126, height 501
"LG L29K_GREEN" [mm] "OSRAM"
  rect 0.8x0.8 smd paste-0.4: 1(-0.75,0) 2(0.75,0)
  silkscreen extent -0.1,-0.5 1.45,0.5, body extent -0.9,-0.45 0.9,0.45, height 0.67
NHD-C12832A1Z-FSW-FBW-3V3 [mm] "TH, 19-Leads, Body 24.3x41.4mm, Pitch 1.5mm"
  rect 1.3x1.3 hole 0.8: 1(0,0)
  round 1.3 hole 0.8: 2(0,-1.5) 3(0,-3) 4(0,-4.5) 5(0,-6) 6(0,-7.5) 7(0,-9) 8(0,-10.5) 9(0,-12) 10(0,-13.5) 11(0,-15) 12(0,-16.5) 13(0,-18) 14(0,-19.5) 15(0,-21) 16(0,-22.5) 17(0,-24)
  round 2.15 hole 1.65: 18(1.95,5.3) 19(1.95,-29.3)
  round 0.75 hole 1.05 unplated: MH1(0,8.1) MH2(0,-32.1) MH3(23.1,-32.1) MH4(23.1,8.1)
  silkscreen extent -0.6,-32.85 24,8.85, body extent -0.6,-32.85 24,8.85, height 4.3
"NY PMS 440 0025 PH" [mm] "4-40 nylon screw and mounting hole"
  round 8 hole 3.2: 1(0,0)
  body extent -3.3,-3.3 3.3,3.3, height 2.69
Panasonic_EVE-JBBF2020B [mm] "TH, 5-Leads, Body 12.4x12.4mm, Pitch 2.5mm"
  rect 1.5x1.5 hole 1: 1(-7.5,2.5)
  round 1.5 hole 1: 2(-7.5,-2.5) 3(7,2.5) 4(7,0) 5(7,-2.5)
  oval 3.1x3 hole 2 slot 2.1 at 0 deg: 6(0,5.6) 7(0,-5.6)
  silkscreen extent -6.75,-6.25 6.25,6.25, body extent -7.6,-6.7 7.1,6.7, height 20.1
Pb-Free_Overlay_Small [mm]
  silkscreen extent -1.16,-1.17 1.17,1.17
PW0028A_N [mm] "TSOP, 28-Leads, Body 9.7x4.4mm, Pitch 0.65mm, IPC Medium Density"
  oval 1.4x0.45 smd: 1(-2.95,4.225) 2(-2.95,3.575) 3(-2.95,2.925) 4(-2.95,2.275) 5(-2.95,1.625) 6(-2.95,0.975) 7(-2.95,0.325) 8(-2.95,-0.325) 9(-2.95,-0.975) 10(-2.95,-1.625) 11(-2.95,-2.275) 12(-2.95,-2.925) 13(-2.95,-3.575) 14(-2.95,-4.225) 15(2.95,-4.225) 16(2.95,-3.575) 17(2.95,-2.925) 18(2.95,-2.275) 19(2.95,-1.625) 20(2.95,-0.975) 21(2.95,-0.325) 22(2.95,0.325) 23(2.95,0.975) 24(2.95,1.625) 25(2.95,2.275) 26(2.95,2.925) 27(2.95,3.575) 28(2.95,4.225)
  silkscreen extent -3.5,-4.9 1.5,4.9, body extent -3.21,-4.85 3.21,4.85, height 1
PWP0020D_L [mm] "SOP, 20-Leads, Body 6.4x4.4mm, Pitch 0.65mm, Thermal Pad 2x3mm, IPC High Density"
  rrect25% 1.2x0.4 smd: 1(-2.85,2.925) 2(-2.85,2.275) 3(-2.85,1.625) 4(-2.85,0.975) 5(-2.85,0.325) 6(-2.85,-0.325) 7(-2.85,-0.975) 8(-2.85,-1.625) 9(-2.85,-2.275) 10(-2.85,-2.925) 11(2.85,-2.925) 12(2.85,-2.275) 13(2.85,-1.625) 14(2.85,-0.975) 15(2.85,-0.325) 16(2.85,0.325) 17(2.85,0.975) 18(2.85,1.625) 19(2.85,2.275) 20(2.85,2.925)
  rrect6% 3.4x6.5 smd paste-2 mask-2: 21(0,0)
  rrect4% 2.4x3.7 on Top Paste: 21(0,0)
  rrect4% 2.4x3.7 on Top Solder: 21(0,0)
  silkscreen extent -2,-3.3 1.5,3.3, body extent -3.21,-3.25 3.21,3.25, height 1
PWP0020D_M [mm] "SOP, 20-Leads, Body 6.4x4.4mm, Pitch 0.65mm, Thermal Pad 2x3mm, IPC Low Density"
  rrect22% 1.6x0.45 smd: 1(-3.05,2.925) 2(-3.05,2.275) 3(-3.05,1.625) 4(-3.05,0.975) 5(-3.05,0.325) 6(-3.05,-0.325) 7(-3.05,-0.975) 8(-3.05,-1.625) 9(-3.05,-2.275) 10(-3.05,-2.925) 11(3.05,-2.925) 12(3.05,-2.275) 13(3.05,-1.625) 14(3.05,-0.975) 15(3.05,-0.325) 16(3.05,0.325) 17(3.05,0.975) 18(3.05,1.625) 19(3.05,2.275) 20(3.05,2.925)
  rrect6% 3.4x6.5 smd paste-2 mask-2: 21(0,0)
  rrect4% 2.4x3.7 on Top Paste: 21(0,0)
  rrect4% 2.4x3.7 on Top Solder: 21(0,0)
  silkscreen extent -3.75,-3.3 1.5,3.4, body extent -3.21,-3.25 3.21,3.25, height 1
SOT-23 [mm] "SOT23, 3-Leads, Body 2.9x1.3mm, Pitch 0.95mm, Lead Span 2.5mm, IPC Medium Density"
  rrect50% 1x0.6 smd: 1(-1.2,0.95) 2(-1.2,-0.95) 3(1.2,0)
  silkscreen extent -1.63,-1.5 0.7,1.5, body extent -1.16,-1.45 1.21,1.45, height 1
Sullins_xxM06DRAN [mm] "Receptacle, 3.96mm, 6x2, TH"
  rect 1.8x1.8 hole 1.3: 1(-1.98,9.9)
  round 1.8 hole 1.3: 2(-1.98,5.94) 3(-1.98,1.98) 4(-1.98,-1.98) 5(-1.98,-5.94) 6(-1.98,-9.9) A(1.98,9.9) B(1.98,5.94) C(1.98,1.98) D(1.98,-1.98) E(1.98,-5.94) F(1.98,-9.9)
  silkscreen extent -14.2,-15.49 -3.2,15.49, body extent -14.18,-15.49 2.29,15.49, height 8.25
SW_SKRKAEE010 [mm] "Alps recommended land pattern"
  rect 0.8x2 smd: 1(-2.1,0) 2(2.1,0)
  silkscreen extent -1.9,-1.44 1.92,1.44, body extent -2.4,-1.45 2.4,1.45, height 1.96
TI_Stacked_Overlay_Small [mm]
  silkscreen extent -10.63,-2.49 10.63,2.49
TPS1HA08-Q1_N [mm] "TSOP, 16-Leads, Body 5x4.4mm, Pitch 0.65mm, Thermal Pad 2.41x3.29 mm, IPC Medium Density"
  rrect22% 1.4x0.45 smd: 1(-2.95,2.275) 2(-2.95,1.625) 3(-2.95,0.975) 4(-2.95,0.325) 5(-2.95,-0.325) 6(-2.95,-0.975) 7(-2.95,-1.625) 8(-2.95,-2.275) 9(2.95,-2.275) 10(2.95,-1.625) 11(2.95,-0.975) 12(2.95,-0.325) 13(2.95,0.325) 14(2.95,0.975) 15(2.95,1.625) 16(2.95,2.275)
  rrect4% 2.5x2.78 on Top Paste: 17(0,-0.155)
  rrect4% 2.5x2.78 on Top Solder: 17(0,-0.155)
  rrect6% 3.4x5 smd paste-1.7 mask-1.7: 17(0,0)
  rrect27% 1.71x0.37 on Top Paste: 17(0,1.36)
  rrect27% 1.71x0.37 on Top Solder: 17(0,1.36)
  silkscreen extent -3.5,-2.55 1.5,2.73, body extent -3.21,-2.5 3.21,2.5, height 0.99
TRANS_NexFET_Q3A [mm] "TI"
  rect 0.68x0.5 smd paste-1 mask+0.076: 1(-1.625,0.975) 2(-1.625,0.325) 3(-1.625,-0.325) 4(-1.625,-0.975)
  rect 0.41x0.5 smd paste-1 mask+0.076: 5(1.385,-0.975) 6(1.385,-0.325) 7(1.385,0.325) 8(1.385,0.975)
  rect 1.96x2.65 smd paste-3 mask+0.076: 9(0.205,0)
  L1 - TOP Component region: 1,1.1 1.24,1.1 1.24,1.325 1,1.325
  L1 - TOP Component region: 1,-1.325 1.24,-1.325 1.24,-1.1 1,-1.1
  silkscreen extent -1.82,-1.7 1.42,1.7, body extent -1.85,-1.65 1.45,1.66, height 0.91
WL-SMCW_Blue_0805 [mm] "SMD, 2-Leads, Body 2x1.25mm"
  rect 1.1x1.2 smd: 1(-1.05,0) 2(1.05,0)
  silkscreen extent -2.4,-1.1 1.5,1.1, body extent -1,-0.62 1,0.63, height 0.7
WL-SMCW_RED_0805 [mm] "SMD, 2-Leads, Body 1.6x0.8mm"
  rect 1.1x1.2 smd: 1(-1.05,0) 2(1.05,0)
  silkscreen extent -2.4,-1.1 1.5,1.1, body extent -1,-0.62 1,0.63, height 0.7

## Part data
AUX_PWR SNS_Filter: "Test Point, Multipurpose, Red, TH"
C1 C2 C3 C4 C5 C6 C7 C8 C9 C10 C11 C12 C13 C14 C15 C16 C17 C18 C19 COUT CV0 CV1 CV2 CV3 CV4: "CAP, CERM, 0.1 µF, 50 V, +/- 20%, X7R, 0805"
D0: "Diode, Switching, 200V, 0.2A, SOT-23"
D1 D2 D3 D4 D5 D6 D7 D8: "LED, Blue, SMD"
D9 D10: "LED, Red, SMD"
D11 D12 D13 D14: "LED, Green, SMD"
DIA_EN(1) DIA_EN(2) EN(1) EN(2) GND_IC SEL1(1) SEL1(2) SEL2(1) SEL2(2) ST(1) ST(2): "Test Point, Miniature, White, TH"
FID1 FID2 FID3: "Fiducial mark.  There is nothing to buy or mount."
GND VBB: "Standard Banana Jack, Uninsulated, 15A"
H1 H2 H3 H4: "Machine Screw, Round, #4-40 x 1/4, Nylon, Philips panhead"
H5 H6 H7 H8: "Standoff, Hex, 0.5\"L #4-40 Nylon"
J1 J2: "Connector, Receptacle, 100mil, 10x1, Gold plated, TH"
J3: "Female Card Edge, 3.96mm, 6x2, Gold, R/A, TH"
J4: "Connector, DC Jack 2.5 mm Center Pin, TH"
Logo1: library part TI_Logo, "Texas Instrument Corporate Signature"
Logo2: library part Pb-Free
Logo3: library part FCC_disclaimer, "FCC_disclaimer"
Q1: "MOSFET, N-CH, 30 V, 19 A, SON 3.3x3.3mm"
R1 R4 R5 R6 R12 R18: "RES, 1.0 k, 5%, 0.1 W, 0603"
R2: "RES, 2.20 k, 1%, 0.1 W, 0603"
R3 R7 R8 R9 R10 R11 R13 R14 R15 R16 R17 R20 R21 R24 R25 R26 R27 R28 R32 R33: "RES, 10 k, 5%, 0.1 W, 0603"
R29: "RES, 47.0 k, 1%, 0.1 W, 0603"
R30 R31 R35 R36: "RES, 1.65 k, 1%, 0.1 W, 0603"
R34: "RES, 10.0 k, 1%, 0.1 W, 0603"
S1 S2: "Switch, Push Button, SMD"
TP_GND1 TP_GND2 TP_GND3: "Test Point, Multipurpose, Black, TH"
U1: "Smart Diode Controller, DGK0008A"
U2: "Automotive 450-mA High-Voltage Ultra-Low IQ Low-Dropout Regulator, PWP0020D (TSSOP-20)"
U3: "450-mA High-Voltage Ultra-Low IQ Low-Dropout Regulator, PWP0020D"
U4: "Six-Channel EMI Filter for LCD Display / Keypad Application, DSV0012A"
U5: "COG Liquid Crystal Display Module, White LED Backlight 3V, SPI I/O, TH"
U6: "Remote 8-Bit I/O Expander for I2C-Bus, 2.5 to 6.0 V, -40 to 85 degC, 16-pin SOIC (DW), Green (RoHS & no Sb/Br)"
U7 U8: library part TPS1HA08CQPWPRQ1, "40-V, 8-mOhm Single-Channel Smart High-Side Switch, TPS1HA08-Q1 (TSSOP-16)"
U10 U11: "ENCODER ROTARY 12MM 20PPR W/SW, TH"
U12: library part TLC59116IPWR, "16-Bit Fast-Mode Plus (FM+) I2C Bus Constant-Current LED Sink Driver, 3 to 5.5 V, -40 to 85 degC, 28-pin SOP (PW28), Green (RoHS & no Sb/Br)"
ZZ1: library part AssemblyNoteLabel
ZZ2 ZZ3 ZZ4: library part AssemblyNote

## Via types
v1: diameter 0.5, hole 0.25, L1 - TOP Component to L4 - BOTTOM Solder, tented both sides, 86 vias
v2: diameter 0.5, hole 0.2, L1 - TOP Component to L4 - BOTTOM Solder, tented both sides, 40 vias
v3: diameter 0.5, hole 0.25, L1 - TOP Component to L4 - BOTTOM Solder, 36 vias
v4: diameter 0.5, hole 0.2, L1 - TOP Component to L4 - BOTTOM Solder, 30 vias
v5: diameter 0.3, hole 0.15, L1 - TOP Component to L4 - BOTTOM Solder, tented both sides, 4 vias

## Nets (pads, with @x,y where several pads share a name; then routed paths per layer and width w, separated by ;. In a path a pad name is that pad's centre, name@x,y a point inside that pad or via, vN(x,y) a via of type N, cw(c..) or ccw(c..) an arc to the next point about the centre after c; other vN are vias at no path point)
+3.3V: AUX_PWR.1 C12.1 J1.1 J3.D R18.1 R26.2 R27.2 R28.2 R29.2 R30.2 R31.2 R32.2 R33.2 S1.1 S2.1 U2.4 U5.12 U5.18 U6.16 | length 318.7
  L1 - TOP Component w0.254: C12.1@41.618,61.908 C12.1@41.783,61.743 ; 58.991,54.902 R26.2@67.666,54.902 ; J1.1@64.77,79.248 J1.1@65.074,78.944 ; J1.1@65.024,79.502 67.742,82.22 ; 67.77,82.248 v1(91.916,82.248) ; S2.1@80.968,11.105 79.801,11.105 79.019,11.887 79.019,16.459 79.793,17.233 S1.1@81.002,17.233 82.968,17.233 89.789,24.054 89.789,25.933 86.843,28.88 ; S2.1@80.983,11.09 82.662,11.09 88.265,5.486 100.317,5.486 R30.2@101.638,6.807 R32.2@101.638,8.75 ; v1(91.897,80.416) 91.897,76.302 U6.16@91.948,76.251 ; R31.2@101.638,34.722 R33.2@101.638,36.661 104.461,36.661 105.486,35.636 115.242,35.636 J3.D@118.924,39.318 ; R27.2@105.118,64.008 R28.2@105.118,66.548 103.022,66.548 96.672,72.898 91.186,72.898 90.678,73.406 90.678,75.438 91.313,76.073 U6.16@92.126,76.073 101.257,76.073 R29.2@106.68,70.65
  L1 - TOP Component w0.4: AUX_PWR.1@48.997,66.548 52.222,63.322 52.222,61.671 58.991,54.902 85.014,28.88 86.843,28.88 98.73,28.88 101.638,31.788 R31.2@101.638,34.722
  L1 - TOP Component w0.5: U5.18@23.656,77.388 44.53,77.388 45.456,76.462 U5.12@45.456,75.438
  L1 - TOP Component w0.6: U2.4@38.379,60.35 40.198,60.366 C12.1@41.618,61.786
  L1 - TOP Component w1: U5.18@23.656,77.388 23.656,69.308 26.365,66.599 42.748,66.599 ; C12.1@41.618,61.786 41.618,61.908 R18.1@41.618,64.008 41.618,65.469 42.748,66.599 ; AUX_PWR.1@48.946,66.599 42.748,66.599
  L4 - BOTTOM Solder w0.254: J1.1@64.77,79.248 J1.1@65.024,79.502 ; v1(91.897,80.416) 91.897,82.229 v1(91.916,82.248)
  L4 - BOTTOM Solder w0.4: AUX_PWR.1@48.997,66.548 52.73,70.282 53.518,70.282 62.484,79.248
  L4 - BOTTOM Solder w0.5: 62.484,79.248 J1.1@64.77,79.248
+5.0V: C6.1 D1.2 D2.2 D3.2 D4.2 D5.2 D6.2 D7.2 D8.2 D9.2 D10.2 R1.1 R34.1 U3.4 U12.28 | length 233.6
  L1 - TOP Component w0.254: D2.2@17.063,29.534 D2.2@17.221,29.693 ; C6.1@20.574,48.006 C6.1@21.082,48.006 ; U12.28@47.486,49.514 50.473,49.514 R34.1@50.546,49.441
  L1 - TOP Component w0.381: U12.28@47.486,49.514 47.486,53.289
  L1 - TOP Component w0.5: D2.2@17.063,29.534 16.256,28.727 16.256,21.463 18.821,18.898 18.821,16.578 D1.2@17.247,15.003 17.247,9.119 21.717,4.648 36.652,4.648 40.895,8.891 D4.2@40.895,14.952 39.604,16.243 39.604,24.999 41.758,27.153 41.758,28.88 D3.2@41.078,29.56 ; D2.2@17.221,29.693 19.738,29.693 D10.2@27.863,37.817 30.883,37.817 v1(33.299,40.234) ; R1.1@19.012,52.108 19.558,51.562 19.558,49.022 C6.1@20.574,48.006 ; R1.1@19.05,52.324 20.066,53.34 20.117,53.289 v1(27.991,53.289) 47.486,53.289 52.984,53.289 60.334,45.94 D9.2@60.334,37.817 63.023,35.128 70.714,35.128 73.59,32.252 D7.2@73.59,29.433 74.727,28.296 74.727,15.367 74.286,14.927 D8.2@73.381,14.927 ; C6.1@21.082,48.006 21.377,47.711 U3.4@22.958,47.711 ; D4.2@40.946,15.003 D5.2@49.581,15.003 50.876,16.298 50.876,28.107 D6.2@49.55,29.434
  L4 - BOTTOM Solder w0.5: v1(27.991,53.289) 33.299,47.981 v1(33.299,40.234)
DIA_EN(1): DIA_EN(1).1 R14.1 U6.6 | length 38.1
  L1 - TOP Component w0.254: U6.6@82.626,69.723 90.764,69.723 91.399,69.088 93.099,69.088 93.472,68.715 93.472,68.047 94.793,66.726 v1(94.767,66.751) ; 92.964,46.482 R14.1@96.19,46.482
  L4 - BOTTOM Solder w0.254: 92.964,46.482 92.964,48.641 94.793,50.47 94.767,50.495 v1(94.767,66.751)
DIA_EN(1)_IC: R14.2 U8.16 | length 33.3
  L1 - TOP Component w0.254: R14.2@97.955,46.482 98.781,47.308 98.781,53.34 100.278,54.837 104.675,54.837 105.102,54.41 113.992,54.41 116.332,52.07 116.332,47.727 115.726,47.121 U8.16@114.19,47.121
DIA_EN(2): DIA_EN(2).1 R8.1 U6.7 | length 60.8
  L1 - TOP Component w0.254: U6.7@82.626,68.453 85.994,68.453 90.043,64.404 v1(90.043,61.9) ; v1@90.043,19.558 91.567,18.034 92.964,18.034 R8.1@96.355,18.034
  L4 - BOTTOM Solder w0.254: v1(90.036,19.637) 90.043,19.644 v1(90.043,61.9)
DIA_EN(2)_IC: R8.2 U7.16 | length 34.7
  L1 - TOP Component w0.254: R8.2@98.018,18.034 98.018,19.253 100.076,21.311 100.076,26.169 104.183,30.277 112.477,30.277 115.37,27.384 115.37,21.111 115.076,20.817 U7.16@114.202,20.817
EN(1): D11.1 EN(1).1 J2.2 R13.1 | length 35.8
  L1 - TOP Component w0.254: 92.964,41.656 92.989,41.631 ; 93.015,41.605 D11.1@96.126,41.605 96.126,41.77 97.155,42.799 ; R13.1@100.063,42.478 98.187,42.478 97.866,42.799 97.155,42.799 ; J2.2@109.728,58.928 98.298,58.928 97.155,57.785 97.155,42.799
EN(1)_IC: R13.2 U8.4 | length 8.2
  L1 - TOP Component w0.254: R13.2@101.638,42.478 101.638,43.288 103.521,45.171 U8.4@108.29,45.171
EN(2): D13.1 EN(2).1 J2.1 R7.1 | length 63.9
  L1 - TOP Component w0.254: 92.989,13.437 D13.1@96.126,13.437 97.145,14.456 R7.1@100.063,14.456
  L4 - BOTTOM Solder w0.254: 92.964,13.462 91.681,14.745 91.681,33.861 92.415,34.595 94.183,34.595 94.996,35.408 94.996,49.249 102.135,56.388 J2.1@109.728,56.388
EN(2)_IC: R7.2 U7.4 | length 9.5
  L1 - TOP Component w0.254: R7.2@101.638,14.573 104.464,14.573 106.172,16.281 106.172,18.085 106.954,18.867 U7.4@108.302,18.867
ENCODER_L_A: C16.1 J1.8 R20.2 | length 98
  L1 - TOP Component w0.254: R20.2@24.917,8.827 24.917,10.833 ; 24.917,10.859 24.917,13.462 ; C16.1@35.458,8.814 35.458,11.862 34.62,12.7 28.071,12.7 27.309,13.462 24.917,13.462 ; v1(38.176,44.78) 38.176,40.665 24.917,27.407 24.917,13.462
  L4 - BOTTOM Solder w0.254: v1(38.176,44.78) 38.176,53.569 40.183,55.575 44.577,55.575 46.66,57.658 65.278,57.658 66.192,58.572 66.192,60.046 J1.8@64.77,61.468
ENCODER_L_B: C15.1 J2.9 R21.2 | length 135.3
  L1 - TOP Component w0.254: R21.2@22.87,8.827 23.482,8.827 24.232,8.077 25.883,8.077 26.492,8.687 C15.1@32.283,8.687 33.35,7.62 36.474,7.62 38.608,9.754 v1(38.608,20.828)
  L4 - BOTTOM Solder w0.254: v1(38.608,20.828) 45.288,27.508 45.288,48.565 51.13,54.407 72.796,54.407 95.098,76.708 J2.9@109.728,76.708
ENCODER_R_A: C18.1 J2.8 R24.2 | length 108.8
  L1 - TOP Component w0.254: R24.2@57.615,8.863 57.615,12.911 v1(58.166,13.462) 59.36,13.462 60.528,12.294 66.446,12.294 67.387,11.353 C18.1@67.387,8.672
  L4 - BOTTOM Solder w0.254: v1(58.166,13.462) 58.166,38.275 67.82,47.93 68.287,47.93 93.916,73.558 109.118,73.558 J2.8@109.728,74.168
ENCODER_R_B: C17.1 J2.3 R25.2 | length 114.2
  L1 - TOP Component w0.254: R25.2@55.456,8.863 55.606,8.863 56.38,8.088 61.367,8.088 61.951,8.672 C17.1@64.339,8.672 64.429,8.672 65.405,7.696 68.234,7.696 68.979,8.441 68.979,12.857 ; v1(64.833,17.018) 68.986,12.865
  L4 - BOTTOM Solder w0.254: v1@64.77,17.018 64.77,44.412 67.957,47.6 68.424,47.6 94.053,73.228 97.968,73.228 J2.3@109.728,61.468
GND: C2.2 C3.2 C4.2 C5.2 C6.2 C7.1 C8.1 C9.2 C10.1 C11.1 C12.2 C15.2 C16.2 C17.2 C18.2 C19.1 COUT.1 CV0.1 CV1.1 CV2.1 CV3.1 CV4.1 D0.3 GND.1 J2.10 J3.2 J3.6 J3.B J3.C J3.F J4.2 J4.3 R2.1 R4.1 R5.2 R6.2 R12.1 R35.1 R36.1 TP_GND1.1 TP_GND2.1 TP_GND3.1 U2.8 U2.13 U2.21@35.915,61.341 U3.8 U3.13 U3.21@25.908,46.736 U4.13 U5.11 U5.19 U6.1 U6.2 U6.3 U6.8 U7.3 U8.3 U10.3 U10.4 U10.5 U10.6 U10.7 U11.3 U11.4 U11.5 U11.6 U11.7 U12.2 U12.3 U12.4 U12.5 U12.10 U12.19 U12.24 | length 181.2
  L1 - TOP Component w0.254: U2.21@35.462,61.341 35.462,60.888 U2.21@35.915,60.888 ; U2.21@35.915,58.56 v2(35.915,58.741) v4(35.915,60.041) U2.21@35.915,60.888 ; U2.21@35.916,59.868 U2.21@35.916,60.888 ; U2.21@36.302,62.204 U2.21@36.986,62.204 ; U2.21@36.369,61.153 36.562,61.347 36.562,61.529 36.828,61.794 U2.21@37.01,61.794 ; R12.1@37.386,49.607 38.129,48.864 U12.2@41.586,48.864 ; U12.10@41.586,43.664 42.547,43.664 42.977,44.094 42.977,46.584 42.646,46.914 U12.5@41.586,46.914 ; U12.19@47.013,43.664 46.39,44.287 46.39,46.382 46.923,46.914 U12.24@47.486,46.914 ; C19.1@70.079,54.458 C19.1@70.838,54.458 ; v1(80.772,73.914) 81.153,73.533 U6.3@82.626,73.533 ; v1(80.772,74.676) 80.899,74.803 U6.2@82.626,74.803 ; v1(80.772,75.438) 81.407,76.073 U6.1@82.626,76.073 ; v1(81.153,67.183) U6.8@82.626,67.183 ; R36.1@101.638,12.633 100.813,13.459 100.813,16.027 102.819,18.034 v1(104.394,18.034) ; R35.1@101.638,40.541 101.638,41.216 100.889,41.965 100.889,45.74 v3(102.215,47.066) 105.264,47.066 D0.3@105.34,46.99 D0.3@105.41,47.06 ; R2.1@104.89,19.228 R2.1@104.902,19.228 ; C9.2@106.9,26.378 105.816,25.294 105.816,23.744 105.487,23.414 104.523,23.414 104.223,23.114 104.223,19.591 R2.1@104.902,18.912 105.507,19.517 U7.3@108.302,19.517 108.942,19.517 109.296,19.163 109.296,15.723 109.449,15.57 112.976,15.57 113.155,15.75 113.155,24.284 113.132,24.308 ; U8.3@108.29,45.821 109.322,45.821 109.322,42.22 109.657,41.885 112.928,41.885 113.132,42.088 113.132,42.31 113.143,42.322 113.143,47.37 113.132,47.382 113.132,50.343 ; U2.21@35.915,60.888 v4(35.915,61.341) U2.21@35.916,60.888
  L1 - TOP Component w0.4: C19.1@70.838,54.458 72.009,55.629 v1(72.009,55.753)
  L1 - TOP Component w0.457: D0.3@105.547,46.99 106.716,45.821 U8.3@108.29,45.821
  L1 - TOP Component w0.5: U3.8@22.958,45.111 30.633,45.111 33.02,47.498 C4.2@33.02,49.022 ; U2.13@32.614,62.967 U2.8@39.243,62.967 ; U12.10@42.109,43.664 U12.19@47.013,43.664 ; v1(97.028,67.056) v1(97.028,71.374) ; R4.1@104.686,49.784 105.41,49.06 D0.3@105.41,47.06 ; D0.3@105.34,46.99 D0.3@105.547,46.99
  L1 - TOP Component w1: v3(30.856,58.216) 31.598,57.474 34.83,57.474 U2.21@35.915,58.56 ; U5.11@43.956,75.438 44.206,75.188 44.206,74.92 44.938,74.188 45.206,74.188 46.482,72.898 v3(46.482,71.628)
  L1 - TOP Component w1.2: C3.2@43.815,59.153 C12.2@43.815,61.743 ; C9.2@106.9,26.378 106.9,27.652 107.696,28.448 111.76,28.448 112.268,27.94 C7.1@112.268,26.924
  L1 - TOP Component w1.3: GND.1@9.373,49.301 10.668,48.006 C6.2@18.542,48.006 C5.2@18.542,50.292
  L4 - BOTTOM Solder w0.254: U5.19@58.206,77.438 U5.19@58.256,77.388
  L4 - BOTTOM Solder w1: U5.11@43.956,75.438 43.956,75.96 45.434,77.438 U5.19@58.206,77.438
  other v1: 63.577,5.777 64.339,5.777 65.101,5.777 66.625,5.777 67.387,5.777 68.149,5.777 31.521,6.096 32.283,6.096 33.045,6.096 34.569,6.096 35.331,6.096 36.093,6.096 104.902,17.526 105.41,18.034 114.376,24.536 114.376,25.298 114.376,26.06 40.218,47.194 39.802,47.955 40.386,48.539 38.964,48.59
  other v2: 24.808,44.136 25.908,44.136 27.008,44.136 24.808,49.336 25.908,49.336 27.008,49.336 34.815,58.741 37.015,58.741 34.815,63.941 35.915,63.941 37.015,63.941
  other v3: 114.376,26.822 34.544,48.26 34.544,49.022 34.544,49.784 114.275,50.292 114.275,51.223 114.275,52.155 114.275,53.086 29.332,58.216 30.094,58.216 45.136,58.344 45.136,59.169 45.136,59.995 26.416,69.088 27.432,69.088 28.448,69.088 29.972,69.088 30.988,69.088 32.512,69.088 33.528,69.088 35.052,69.088 36.068,69.088 37.084,69.088 46.482,70.866
  other v4: 24.808,45.436 25.908,45.436 27.008,45.436 24.808,46.736 25.908,46.736 27.008,46.736 24.808,48.036 25.908,48.036 27.008,48.036 34.815,60.041 37.015,60.041 34.815,61.341 37.015,61.341 34.815,62.641 35.915,62.641 37.015,62.641
  other v5: 49.022,71.374 49.53,71.374 50.038,71.374 50.572,71.374
INT: C19.2 J1.10 R26.1 U6.13 | length 36.2
  L1 - TOP Component w0.254: J1.10@64.808,56.426 J1.10@64.77,56.388 67.551,56.388 R26.1@67.653,56.49 ; R26.1@67.666,56.502 71.666,56.502 78.13,62.967 78.13,66.827 81.661,70.358 83.82,70.358 85.725,72.263 U6.13@92.126,72.263
NetC1_1: C1.1 U1.7 | length 4
  L1 - TOP Component w0.5: U1.7@20.897,55.891 20.897,56.965 21.336,57.404 C1.1@23.622,57.404
NetC1_2: C1.2 U1.1 | length 2.7
  L1 - TOP Component w0.5: U1.1@21.547,60.341 21.547,59.703 22.068,59.182 C1.2@23.368,59.182
NetC3_1: C3.1 U2.3 | length 3.2
  L1 - TOP Component w0.254: U2.3@38.865,59.716 39.674,59.716 40.237,59.153 C3.1@41.783,59.153
NetC5_1: C5.1 U3.3 | length 3.4
  L1 - TOP Component w0.254: C5.1@20.574,50.292 21.59,49.276 21.59,48.92 22.149,48.361 U3.3@22.958,48.361
NetC13_1: C13.1 U5.8 | length 5.8
  L1 - TOP Component w0.254: U5.8@39.456,75.438 39.456,74.59 40.64,73.406 40.64,71.882 C13.1@41.91,70.612
NetC13_2: C13.2 U5.9 | length 3.2
  L1 - TOP Component w0.254: U5.9@40.956,75.438 40.956,73.598 C13.2@41.91,72.644
NetC14_1: C14.1 U5.7 | length 3.4
  L1 - TOP Component w0.254: U5.7@37.956,75.438 37.956,74.058 C14.1@39.37,72.644
NetC14_2: C14.2 U5.6 | length 6
  L1 - TOP Component w0.254: U5.6@36.456,75.438 36.456,74.774 38.1,73.13 38.1,71.882 C14.2@39.37,70.612
NetCOUT_2: COUT.2 U5.10 | length 3.6
  L1 - TOP Component w0.254: U5.10@42.456,75.438 42.456,74.638 COUT.2@44.45,72.644
NetCV0_2: CV0.2 U5.1 | length 3.7
  L1 - TOP Component w0.254: CV0.2@26.67,72.644 26.67,73.152 U5.1@28.956,75.438
NetCV1_2: CV1.2 U5.2 | length 3.3
  L1 - TOP Component w0.254: CV1.2@29.21,72.644 29.21,73.66 30.456,74.906 U5.2@30.456,75.438
NetCV2_2: CV2.2 U5.3 | length 2.9
  L1 - TOP Component w0.254: CV2.2@31.75,72.644 31.75,75.232 U5.3@31.956,75.438
NetCV3_2: CV3.2 U5.4 | length 3.1
  L1 - TOP Component w0.254: U5.4@33.456,75.438 33.456,73.478 CV3.2@34.29,72.644
NetCV4_2: CV4.2 U5.5 | length 3.6
  L1 - TOP Component w0.254: U5.5@34.956,75.438 34.956,74.518 CV4.2@36.83,72.644
NetD0_1: D0.1 GND_IC.1 R4.2 U7.1 U8.1 | length 49.9
  L1 - TOP Component w0.254: D0.1@103.086,48.086 R4.2@103.086,49.784 103.811,50.509 105.447,50.509 106.403,49.553 106.403,48.308 107.59,47.121 U8.1@108.29,47.121 ; 103.886,50.584 GND_IC.1@103.886,53.594 ; v1(107.036,21.996) 107.036,21.082 107.301,20.817 U7.1@108.302,20.817
  L4 - BOTTOM Solder w0.254: GND_IC.1@103.886,53.594 101.016,50.724 101.016,28.499 107.036,22.479 v1(107.036,21.996)
NetD1_1: D1.1 U12.6 | length 50.6
  L1 - TOP Component w0.254: D1.1@17.247,17.103 14.859,19.49 14.859,35.585 21.133,41.859 30.251,41.859 34.657,46.264 U12.6@41.586,46.264
NetD2_1: D2.1 U12.7 | length 33.4
  L1 - TOP Component w0.254: D2.1@18.548,31.019 18.548,38.411 21.387,41.25 30.556,41.25 34.952,45.645 41.555,45.645 U12.7@41.586,45.614
NetD3_1: D3.1 U12.8 | length 16.4
  L1 - TOP Component w0.254: D3.1@39.593,31.045 38.76,31.877 38.76,43.781 39.944,44.964 U12.8@41.586,44.964
NetD4_1: D4.1 U12.9 | length 31.1
  L1 - TOP Component w0.254: D4.1@40.895,17.052 43.104,19.262 43.104,35.865 39.685,39.284 39.685,43.689 40.31,44.314 U12.9@41.586,44.314
NetD5_1: D5.1 U12.11 | length 31.1
  L1 - TOP Component w0.254: U12.11@41.586,43.014 40.508,43.014 40.091,42.597 40.091,39.538 47.676,31.953 47.676,28.804 49.581,26.899 D5.1@49.581,17.103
